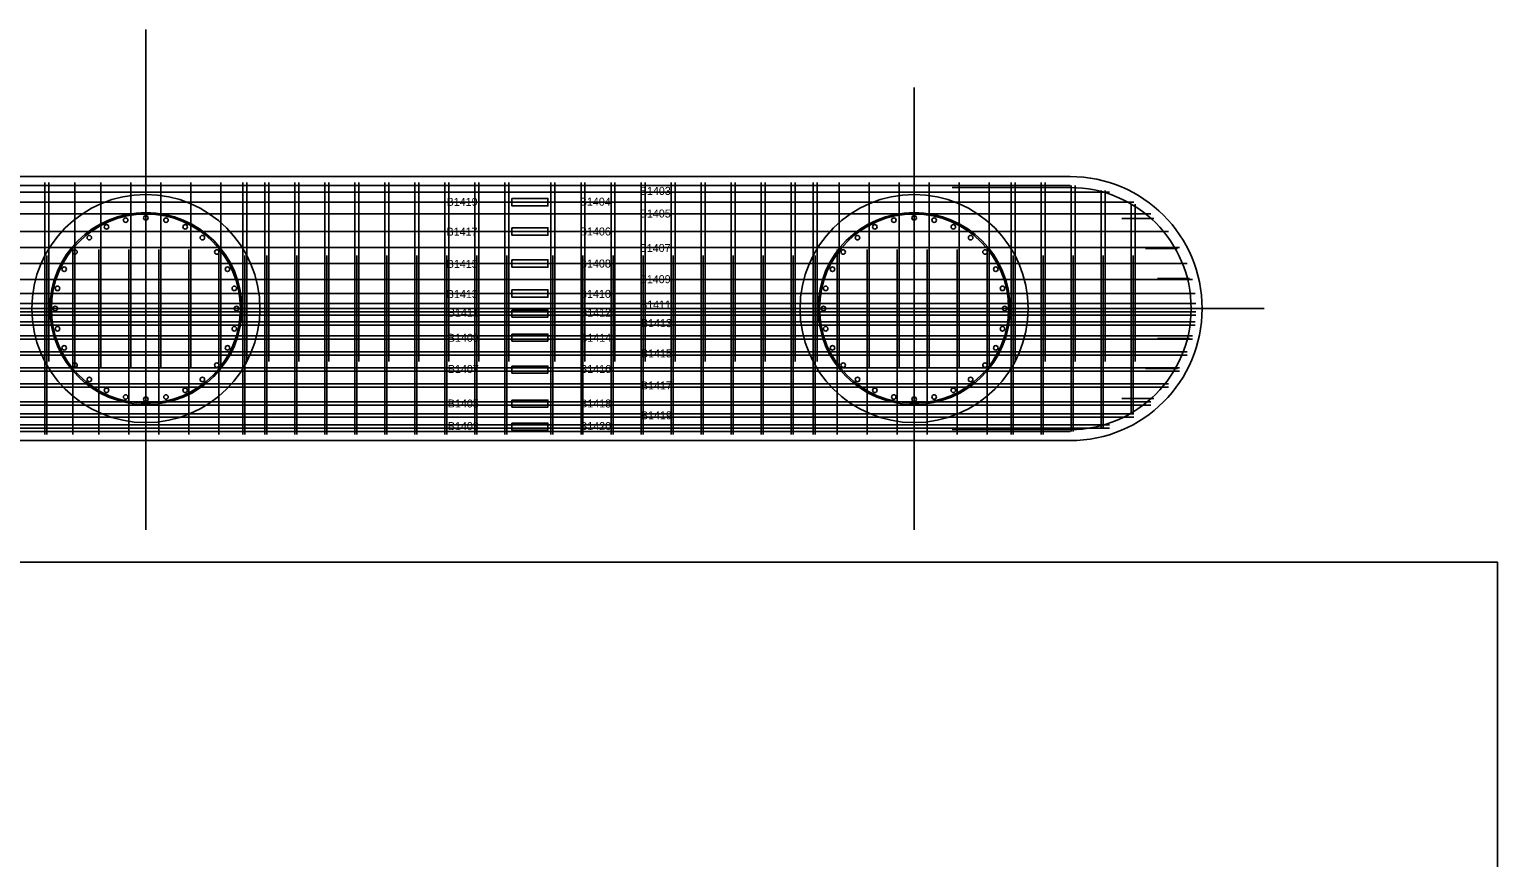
# Model space of a CAD drawing. Extents: x 653466 to 653585, y 408325 to 408579.
# Drawn here: x 653520 to 653581.2, y 408377.1 to 408411.6 of the extents above; entities that cross this region are included whole.
import ezdxf

# ---------------------------------------------------------------- set-up
doc = ezdxf.new("R2010")
doc.units = 0
for name, color, linetype in [('B_Boring', 7, 'Continuous'), ('B_Boring Annot', 7, 'Continuous'), ('BD-PROP-OSB', 7, 'Continuous'), ('R_Anno_Text', 7, 'Continuous'), ('R_Proposed Const Limits Fill', 7, 'Continuous'), ('R_Shade By Others', 7, 'Continuous'), ('R_Shade Removal', 7, 'Continuous'), ('R_Survey Control', 7, 'Continuous'), ('R_Wall', 7, 'Continuous')]:
    doc.layers.add(name, color=color, linetype=linetype)

msp = doc.modelspace()

# ---------------------------------------------------------------- linework, layer by layer
at = {"layer": 'B_Boring'}
msp.add_line((653571.459, 408399.933), (653476.296, 408399.933), dxfattribs=at)
at = {"layer": 'B_Boring Annot'}
for centre in [(653524.878, 408399.933), (653556.878, 408399.933)]:
    msp.add_circle(centre, 4.75, dxfattribs=at)
at = {"layer": 'BD-PROP-OSB'}
for p, q in [((653531.086, 408405.183), (653531.086, 408394.683)), ((653531.253, 408405.183), (653531.253, 408397.725)), ((653532.336, 408405.183), (653532.336, 408394.683)), ((653532.503, 408405.183), (653532.503, 408397.725)), ((653533.586, 408405.183), (653533.586, 408394.683)), ((653533.753, 408405.183), (653533.753, 408397.725)), ((653534.836, 408405.183), (653534.836, 408394.683)), ((653535.003, 408405.183), (653535.003, 408397.725)), ((653536.086, 408405.183), (653536.086, 408394.683)), ((653536.253, 408405.183), (653536.253, 408397.725)), ((653537.336, 408405.183), (653537.336, 408394.683)), ((653537.503, 408405.183), (653537.503, 408397.725)), ((653538.586, 408405.183), (653538.586, 408394.683)), ((653538.753, 408405.183), (653538.753, 408397.725)), ((653543.003, 408405.183), (653543.003, 408394.683)), ((653543.169, 408405.183), (653543.169, 408397.725)), ((653544.253, 408405.183), (653544.253, 408394.683)), ((653544.419, 408405.183), (653544.419, 408397.725)), ((653545.503, 408405.183), (653545.503, 408394.683)), ((653545.669, 408405.183), (653545.669, 408397.725)), ((653546.753, 408405.183), (653546.753, 408394.683)), ((653546.919, 408405.183), (653546.919, 408397.725)), ((653548.003, 408405.183), (653548.003, 408394.683)), ((653548.169, 408405.183), (653548.169, 408397.725)), ((653549.253, 408405.183), (653549.253, 408394.683)), ((653549.419, 408405.183), (653549.419, 408397.725)), ((653550.503, 408405.183), (653550.503, 408394.683)), ((653550.669, 408405.183), (653550.669, 408397.725)), ((653531.169, 408402.141), (653531.169, 408394.683)), ((653532.419, 408402.141), (653532.419, 408394.683)), ((653533.669, 408402.141), (653533.669, 408394.683)), ((653534.919, 408402.141), (653534.919, 408394.683)), ((653536.169, 408402.141), (653536.169, 408394.683)), ((653537.419, 408402.141), (653537.419, 408394.683)), ((653538.669, 408402.141), (653538.669, 408394.683)), ((653543.086, 408402.141), (653543.086, 408394.683)), ((653544.336, 408402.141), (653544.336, 408394.683)), ((653545.586, 408402.141), (653545.586, 408394.683)), ((653546.836, 408402.141), (653546.836, 408394.683)), ((653548.086, 408402.141), (653548.086, 408394.683)), ((653549.336, 408402.141), (653549.336, 408394.683)), ((653550.586, 408402.141), (653550.586, 408394.683))]:
    msp.add_line(p, q, dxfattribs=at)
at = {"layer": 'R_Anno_Text'}
msp.add_line((653524.878, 408390.721), (653524.878, 408411.562), dxfattribs=at)
at = {"layer": 'R_Proposed Const Limits Fill'}
for p, q in [((653486.378, 408405.058), (653563.378, 408405.058)), ((653520.669, 408405.183), (653520.669, 408394.683)), ((653520.836, 408405.183), (653520.836, 408397.725)), ((653521.92, 408405.183), (653521.92, 408397.475)), ((653523.003, 408405.183), (653523.003, 408397.475)), ((653524.253, 408405.183), (653524.253, 408397.475)), ((653525.503, 408405.183), (653525.503, 408397.475)), ((653526.753, 408405.183), (653526.753, 408397.475)), ((653528.003, 408405.183), (653528.003, 408397.475)), ((653528.919, 408405.183), (653528.919, 408394.683)), ((653529.086, 408405.183), (653529.086, 408397.725)), ((653529.836, 408405.183), (653529.836, 408394.683)), ((653530.003, 408405.183), (653530.003, 408397.725)), ((653539.836, 408405.183), (653539.836, 408394.683)), ((653540.003, 408405.183), (653540.003, 408397.725)), ((653541.753, 408405.183), (653541.753, 408394.683)), ((653541.919, 408405.183), (653541.919, 408397.725)), ((653551.753, 408405.183), (653551.753, 408394.683)), ((653551.919, 408405.183), (653551.919, 408397.725)), ((653552.669, 408405.183), (653552.669, 408394.683)), ((653552.836, 408405.183), (653552.836, 408397.725)), ((653553.753, 408405.183), (653553.753, 408397.475)), ((653555.003, 408405.183), (653555.003, 408397.475)), ((653556.253, 408405.183), (653556.253, 408397.475)), ((653557.503, 408405.183), (653557.503, 408397.475)), ((653558.753, 408405.183), (653558.753, 408397.475)), ((653560.003, 408405.183), (653560.003, 408397.475)), ((653560.919, 408405.183), (653560.919, 408394.683)), ((653561.086, 408405.183), (653561.086, 408397.725)), ((653562.169, 408405.183), (653562.169, 408394.683)), ((653562.336, 408405.183), (653562.336, 408397.725)), ((653563.419, 408405.054), (653563.419, 408394.809)), ((653563.586, 408405.054), (653563.586, 408397.725)), ((653508.878, 408404.779), (653565.018, 408404.779)), ((653563.378, 408404.975), (653558.461, 408404.975)), ((653564.669, 408404.846), (653564.669, 408394.996)), ((653564.836, 408404.846), (653564.836, 408397.725)), ((653483.722, 408404.362), (653540.878, 408404.362)), ((653508.878, 408403.881), (653566.744, 408403.881)), ((653540.878, 408404.362), (653566.033, 408404.362)), ((653565.919, 408404.284), (653565.919, 408395.531)), ((653566.086, 408404.284), (653566.086, 408397.725)), ((653482.278, 408403.141), (653540.878, 408403.141)), ((653540.878, 408403.141), (653567.478, 408403.141)), ((653566.871, 408403.683), (653565.538, 408403.683)), ((653508.878, 408402.475), (653567.932, 408402.475)), ((653520.753, 408402.141), (653520.753, 408394.683)), ((653521.836, 408402.391), (653521.836, 408394.683)), ((653522.92, 408402.391), (653522.92, 408394.683)), ((653524.17, 408402.391), (653524.17, 408394.683)), ((653525.42, 408402.391), (653525.42, 408394.683)), ((653526.67, 408402.391), (653526.67, 408394.683)), ((653527.92, 408402.391), (653527.92, 408394.683)), ((653529.003, 408402.141), (653529.003, 408394.683)), ((653529.919, 408402.141), (653529.919, 408394.683)), ((653539.919, 408402.141), (653539.919, 408394.683)), ((653541.836, 408402.141), (653541.836, 408394.683)), ((653551.836, 408402.141), (653551.836, 408394.683)), ((653552.753, 408402.141), (653552.753, 408394.683)), ((653553.67, 408402.391), (653553.67, 408394.683)), ((653554.92, 408402.391), (653554.92, 408394.683)), ((653556.17, 408402.391), (653556.17, 408394.683)), ((653557.42, 408402.391), (653557.42, 408394.683)), ((653558.67, 408402.391), (653558.67, 408394.683)), ((653559.92, 408402.391), (653559.92, 408394.683)), ((653561.003, 408402.141), (653561.003, 408394.683)), ((653562.253, 408402.141), (653562.253, 408394.683)), ((653563.503, 408402.141), (653563.503, 408394.809)), ((653564.753, 408402.141), (653564.753, 408394.996)), ((653566.003, 408402.141), (653566.003, 408395.531)), ((653567.852, 408402.433), (653566.518, 408402.433)), ((653481.502, 408401.808), (653540.878, 408401.808)), ((653540.878, 408401.808), (653568.254, 408401.808)), ((653508.878, 408401.141), (653568.47, 408401.141)), ((653568.348, 408401.183), (653567.015, 408401.183)), ((653481.174, 408400.558), (653540.878, 408400.558)), ((653508.878, 408400.141), (653568.62, 408400.141)), ((653540.878, 408400.558), (653568.582, 408400.558)), ((653481.132, 408399.795), (653540.878, 408399.795)), ((653481.132, 408399.654), (653540.878, 408399.654)), ((653540.878, 408399.795), (653568.62, 408399.795)), ((653540.878, 408399.654), (653568.62, 408399.654)), ((653568.503, 408399.933), (653567.17, 408399.933)), ((653508.878, 408399.378), (653568.582, 408399.378)), ((653508.878, 408399.237), (653568.582, 408399.237)), ((653481.286, 408398.795), (653540.878, 408398.795)), ((653481.286, 408398.654), (653540.878, 408398.654)), ((653540.878, 408398.795), (653568.47, 408398.795)), ((653540.878, 408398.654), (653568.47, 408398.654)), ((653568.348, 408398.683), (653567.015, 408398.683)), ((653508.878, 408398.128), (653568.254, 408398.128)), ((653508.878, 408397.987), (653568.254, 408397.987)), ((653481.824, 408397.462), (653540.878, 408397.462)), ((653481.824, 408397.321), (653540.878, 408397.321)), ((653540.878, 408397.462), (653567.932, 408397.462)), ((653540.878, 408397.321), (653567.932, 408397.321)), ((653567.852, 408397.433), (653566.518, 408397.433)), ((653508.878, 408396.795), (653567.478, 408396.795)), ((653508.878, 408396.654), (653567.478, 408396.654)), ((653483.012, 408396.045), (653540.878, 408396.045)), ((653483.012, 408395.904), (653540.878, 408395.904)), ((653540.878, 408396.045), (653566.744, 408396.045)), ((653540.878, 408395.904), (653566.744, 408395.904)), ((653566.871, 408396.183), (653565.538, 408396.183)), ((653508.878, 408395.545), (653566.033, 408395.545)), ((653508.878, 408395.404), (653566.033, 408395.404)), ((653484.738, 408395.087), (653540.878, 408395.087)), ((653484.738, 408394.946), (653540.878, 408394.946)), ((653486.378, 408394.808), (653563.378, 408394.808)), ((653540.878, 408395.087), (653565.018, 408395.087)), ((653540.878, 408394.946), (653565.018, 408394.946)), ((653563.378, 408394.891), (653558.461, 408394.891))]:
    msp.add_line(p, q, dxfattribs=at)
for points in [[(653540.128, 408404.519), (653541.628, 408404.519), (653541.628, 408404.206), (653540.128, 408404.206)], [(653540.128, 408403.297), (653541.628, 408403.297), (653541.628, 408402.985), (653540.128, 408402.985)], [(653540.128, 408401.964), (653541.628, 408401.964), (653541.628, 408401.652), (653540.128, 408401.652)], [(653540.128, 408400.714), (653541.628, 408400.714), (653541.628, 408400.402), (653540.128, 408400.402)], [(653540.128, 408399.87), (653541.628, 408399.87), (653541.628, 408399.579), (653540.128, 408399.579)], [(653540.128, 408398.87), (653541.628, 408398.87), (653541.628, 408398.579), (653540.128, 408398.579)], [(653540.128, 408397.537), (653541.628, 408397.537), (653541.628, 408397.245), (653540.128, 408397.245)], [(653540.128, 408396.12), (653541.628, 408396.12), (653541.628, 408395.829), (653540.128, 408395.829)], [(653540.128, 408395.162), (653541.628, 408395.162), (653541.628, 408394.87), (653540.128, 408394.87)]]:
    msp.add_lwpolyline(points, close=True, dxfattribs=at)
for centre, radius in [((653524.878, 408399.933), 4), ((653524.878, 408399.933), 3.937), ((653524.878, 408403.709), 0.094), ((653556.878, 408399.933), 4), ((653556.878, 408399.933), 3.937), ((653556.878, 408403.709), 0.094), ((653523.24, 408403.335), 0.094), ((653524.038, 408403.614), 0.094), ((653525.718, 408403.614), 0.094), ((653526.516, 408403.335), 0.094), ((653555.24, 408403.335), 0.094), ((653556.038, 408403.614), 0.094), ((653557.718, 408403.614), 0.094), ((653558.516, 408403.335), 0.094), ((653522.524, 408402.885), 0.094), ((653527.232, 408402.885), 0.094), ((653554.524, 408402.885), 0.094), ((653559.232, 408402.885), 0.094), ((653521.926, 408402.287), 0.094), ((653527.83, 408402.287), 0.094), ((653553.926, 408402.287), 0.094), ((653559.83, 408402.287), 0.094), ((653521.476, 408401.571), 0.094), ((653528.28, 408401.571), 0.094), ((653553.476, 408401.571), 0.094), ((653560.28, 408401.571), 0.094), ((653521.197, 408400.773), 0.094), ((653528.559, 408400.773), 0.094), ((653553.197, 408400.773), 0.094), ((653560.559, 408400.773), 0.094), ((653521.102, 408399.933), 0.094), ((653528.654, 408399.933), 0.094), ((653553.102, 408399.933), 0.094), ((653560.654, 408399.933), 0.094), ((653521.197, 408399.093), 0.094), ((653528.559, 408399.093), 0.094), ((653553.197, 408399.093), 0.094), ((653560.559, 408399.093), 0.094), ((653521.476, 408398.295), 0.094), ((653528.28, 408398.295), 0.094), ((653553.476, 408398.295), 0.094), ((653560.28, 408398.295), 0.094), ((653521.926, 408397.579), 0.094), ((653527.83, 408397.579), 0.094), ((653553.926, 408397.579), 0.094), ((653559.83, 408397.579), 0.094), ((653522.524, 408396.981), 0.094), ((653527.232, 408396.981), 0.094), ((653554.524, 408396.981), 0.094), ((653559.232, 408396.981), 0.094), ((653523.24, 408396.531), 0.094), ((653526.516, 408396.531), 0.094), ((653555.24, 408396.531), 0.094), ((653558.516, 408396.531), 0.094), ((653524.038, 408396.252), 0.094), ((653524.878, 408396.157), 0.094), ((653525.718, 408396.252), 0.094), ((653556.038, 408396.252), 0.094), ((653556.878, 408396.157), 0.094), ((653557.718, 408396.252), 0.094)]:
    msp.add_circle(centre, radius, dxfattribs=at)
for start, end in [(360, 90), (270, 360)]:
    msp.add_arc((653563.378, 408399.933), 5.042, start, end, dxfattribs=at)
at = {"layer": 'R_Shade By Others'}
msp.add_lwpolyline([(653465.958, 408389.369), (653581.187, 408389.369), (653581.187, 408336.489), (653465.958, 408336.489)], close=True, dxfattribs=at)
at = {"layer": 'R_Shade Removal'}
for p, q in [((653486.376, 408405.433), (653563.378, 408405.433)), ((653486.378, 408394.433), (653563.378, 408394.433))]:
    msp.add_line(p, q, dxfattribs=at)
msp.add_arc((653563.378, 408399.933), 5.5, 270, 90, dxfattribs=at)
at = {"layer": 'R_Wall'}
msp.add_line((653556.878, 408390.721), (653556.878, 408409.145), dxfattribs=at)

# ---------------------------------------------------------------- texts
at = {"layer": 'R_Survey Control'}
for s, p in [('B1403', (653545.454, 408404.668)), ('B1419', (653537.406, 408404.211)), ('B1404', (653542.951, 408404.218)), ('B1405', (653545.452, 408403.726)), ('B1417', (653537.403, 408402.97)), ('B1406', (653542.955, 408402.977)), ('B1407', (653545.445, 408402.29)), ('B1415', (653537.41, 408401.626)), ('B1408', (653542.957, 408401.641)), ('B1409', (653545.447, 408400.991)), ('B1413', (653537.413, 408400.371)), ('B1410', (653542.958, 408400.379)), ('B1411', (653545.465, 408399.935)), ('B1411', (653537.457, 408399.598)), ('B1412', (653542.967, 408399.598)), ('B1413', (653545.499, 408399.161)), ('B1409', (653537.457, 408398.549)), ('B1414', (653542.967, 408398.549)), ('B1415', (653545.499, 408397.899)), ('B1407', (653537.457, 408397.25)), ('B1416', (653542.967, 408397.25)), ('B1417', (653545.499, 408396.563)), ('B1405', (653537.457, 408395.813)), ('B1418', (653542.967, 408395.813)), ('B1403', (653537.457, 408394.872)), ('B1420', (653542.967, 408394.872)), ('B1419', (653545.499, 408395.321))]:
    msp.add_text(s, height=0.3333, dxfattribs=at).set_placement(p)

doc.saveas('drawing.dxf')
